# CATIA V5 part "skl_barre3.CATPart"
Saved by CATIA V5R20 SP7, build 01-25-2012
Part number: skl_barre3
Publications: "axe_pivot_3_0", "axe_pivot_3_2", "PointC", "PointD", "PlanRef"
Bounding box of the stored display mesh (mm): x 0 to 20, y 300 to 365.434, z 0 to 292.777
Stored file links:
  U:\Projet IAO\omeyer\Catia\skl_barre3.CATPart
  U:\Projet IAO\omeyer\Catia\skl_748.CATProduct
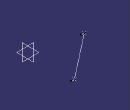
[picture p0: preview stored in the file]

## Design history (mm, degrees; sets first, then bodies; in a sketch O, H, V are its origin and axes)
Set1
  DatumPoint1 "PointC": linked copy from another document
  Point1 "PointD": linked copy from another document
  Plane1 "PlanRef": linked copy from another document
Set2
  Line1: type PtPt, FirstPoint DatumPoint1, SecondPoint Point1
  Line2 "axe_pivot_3_2": type Normal, RefPoint DatumPoint1, RefSkin Plane1, Start 0, End 20
  Line3 "axe_pivot_3_0": type Normal, RefPoint Point1, RefSkin Plane1, Start 0, End 20
Body1 (main body)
